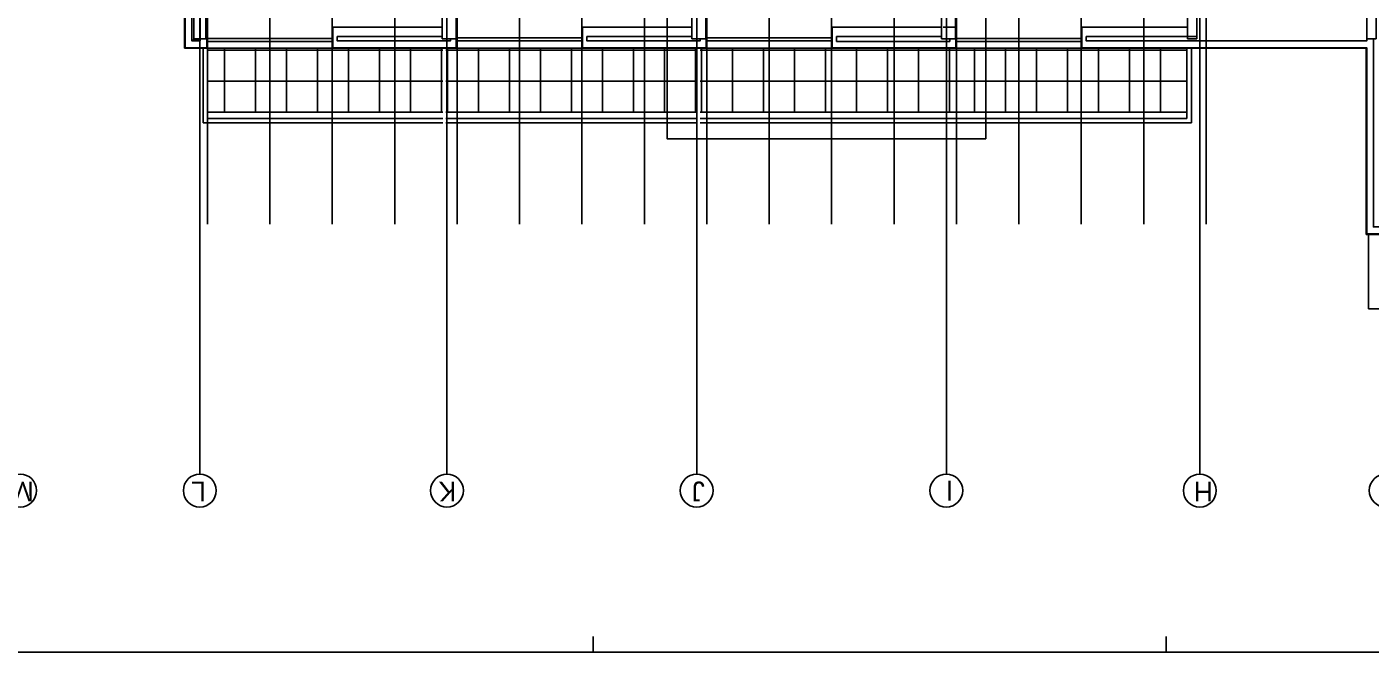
# Model space of a CAD drawing. Extents: x 1248 to 1356, y -443 to -224.
# Drawn here: x 1296.63 to 1318.31, y -253.66 to -243.58 of the extents above; entities that cross this region are included whole.
import ezdxf

# ---------------------------------------------------------------- set-up
doc = ezdxf.new("R2010")
doc.units = 0
for name, color, linetype in [('corte', 7, 'Continuous'), ('estereoctomias', 7, 'Continuous'), ('estrutura-eixos', 7, 'Continuous'), ('Level 1', 7, 'Continuous'), ('Level 10', 7, 'Continuous'), ('Level 2', 7, 'Continuous'), ('Level 40', 7, 'Continuous'), ('Level 59', 7, 'Continuous'), ('Level 62', 7, 'Continuous'), ('revestimentos', 7, 'Continuous'), ('vermelhos-cont', 7, 'Continuous'), ('vermelhos-tracej', 7, 'Continuous')]:
    doc.layers.add(name, color=color, linetype=linetype)

msp = doc.modelspace()

# ---------------------------------------------------------------- linework, layer by layer
at = {"layer": 'corte'}
for p, q in [((1299.423, -238.844), (1299.423, -243.794)), ((1299.533, -243.914), (1299.533, -238.914)), ((1303.562, -243.914), (1303.562, -238.844)), ((1307.592, -243.914), (1307.592, -238.844)), ((1311.622, -243.914), (1311.622, -238.844)), ((1315.513, -238.796), (1315.513, -243.771)), ((1311.389, -240.756), (1311.389, -243.584)), ((1303.329, -243.734), (1301.637, -243.734)), ((1303.464, -243.804), (1301.637, -243.804)), ((1303.464, -243.771), (1303.464, -243.804)), ((1307.359, -243.734), (1305.667, -243.734)), ((1307.494, -243.804), (1305.667, -243.804)), ((1307.494, -243.771), (1307.494, -243.804)), ((1311.389, -243.734), (1309.697, -243.734)), ((1311.524, -243.814), (1309.697, -243.814)), ((1311.524, -243.771), (1311.524, -243.814)), ((1315.513, -243.734), (1313.727, -243.734)), ((1318.254, -243.804), (1318.254, -243.771)), ((1319.284, -246.914), (1318.254, -246.914))]:
    msp.add_line(p, q, dxfattribs=at)
msp.add_lwpolyline([(1299.519, -238.726), (1299.519, -243.774), (1299.321, -243.774), (1299.321, -238.726)], dxfattribs=at)
for points in [[(1315.513, -243.771), (1315.363, -243.771), (1315.363, -241.471), (1315.513, -241.471)], [(1318.404, -243.771), (1318.254, -243.771), (1318.254, -242.171), (1318.404, -242.171)], [(1303.329, -243.771), (1303.559, -243.771), (1303.559, -242.771), (1303.329, -242.771)], [(1307.359, -243.771), (1307.589, -243.771), (1307.589, -242.771), (1307.359, -242.771)], [(1311.389, -243.771), (1311.619, -243.771), (1311.619, -242.771), (1311.389, -242.771)]]:
    msp.add_lwpolyline(points, close=True, dxfattribs=at)
at = {"layer": 'estereoctomias'}
for points in [[(1299.533, -238.914), (1299.983, -238.914), (1299.983, -238.726), (1299.519, -238.726), (1299.519, -238.796), (1299.913, -238.796), (1299.913, -238.844), (1299.519, -238.844), (1299.519, -243.774), (1299.423, -243.774), (1299.423, -243.804), (1299.291, -243.804), (1299.291, -238.796), (1299.321, -238.796), (1299.321, -238.726), (1299.181, -238.726), (1299.181, -243.914), (1299.519, -243.914), (1299.533, -243.914), (1299.53, -240.996), (1299.94, -240.996), (1299.94, -240.926), (1299.533, -240.926)], [(1303.559, -243.771), (1303.559, -243.914), (1301.567, -243.914), (1301.567, -243.584), (1303.329, -243.584), (1303.329, -243.734), (1301.637, -243.734), (1301.637, -243.804), (1303.464, -243.804), (1303.464, -243.771)], [(1307.592, -243.914), (1307.592, -243.771), (1307.494, -243.771), (1307.494, -243.804), (1305.667, -243.804), (1305.667, -243.734), (1307.359, -243.734), (1307.359, -243.584), (1305.597, -243.584), (1305.597, -243.914)], [(1311.524, -243.771), (1311.524, -243.814), (1309.697, -243.814), (1309.697, -243.734), (1311.389, -243.734), (1311.389, -243.584), (1309.627, -243.584), (1309.627, -243.914), (1311.622, -243.914), (1311.622, -243.771)], [(1315.363, -243.584), (1315.363, -243.734), (1313.727, -243.734), (1313.727, -243.804), (1318.254, -243.804), (1318.254, -243.771), (1318.364, -243.771), (1318.363, -246.804), (1319.214, -246.804), (1319.214, -246.734), (1318.63, -246.734), (1318.631, -246.584), (1319.284, -246.584), (1319.284, -246.914), (1318.254, -246.914), (1318.254, -243.914), (1313.657, -243.914), (1313.657, -243.584)]]:
    msp.add_lwpolyline(points, close=True, dxfattribs=at)
at = {"layer": 'estrutura-eixos'}
msp.add_line((1318.283, -246.924), (1318.283, -248.124), dxfattribs=at)
at = {"layer": 'Level 1'}
for p, q in [((1299.181, -243.914), (1299.181, -238.726)), ((1299.291, -243.794), (1299.291, -238.796)), ((1303.329, -243.584), (1301.567, -243.584)), ((1301.567, -243.584), (1301.567, -243.914)), ((1307.359, -243.584), (1305.597, -243.584)), ((1305.597, -243.584), (1305.597, -243.914)), ((1311.389, -243.584), (1309.627, -243.584)), ((1309.627, -243.584), (1309.627, -243.914)), ((1311.418, -243.584), (1311.558, -243.584)), ((1311.483, -243.584), (1311.623, -243.584)), ((1315.363, -243.584), (1313.657, -243.584)), ((1313.657, -243.584), (1313.657, -243.914)), ((1299.291, -243.794), (1299.423, -243.794)), ((1301.637, -243.734), (1301.637, -243.804)), ((1305.667, -243.734), (1305.667, -243.804)), ((1309.697, -243.734), (1309.697, -243.814)), ((1313.727, -243.734), (1313.727, -243.804)), ((1313.727, -243.804), (1318.254, -243.804)), ((1299.181, -243.914), (1299.533, -243.914)), ((1301.567, -243.914), (1303.562, -243.914)), ((1303.224, -243.914), (1303.424, -243.914)), ((1305.597, -243.914), (1307.592, -243.914)), ((1309.627, -243.914), (1311.622, -243.914)), ((1313.657, -243.914), (1318.254, -243.914)), ((1318.254, -243.914), (1318.254, -246.914))]:
    msp.add_line(p, q, dxfattribs=at)
at = {"layer": 'Level 10'}
for p, q in [((1299.542, -243.954), (1303.343, -243.954)), ((1299.818, -244.954), (1299.818, -243.924)), ((1300.318, -244.954), (1300.318, -243.924)), ((1300.818, -244.954), (1300.818, -243.924)), ((1301.318, -244.954), (1301.318, -243.924)), ((1301.818, -244.954), (1301.818, -243.924)), ((1302.318, -244.954), (1302.318, -243.924)), ((1302.818, -244.954), (1302.818, -243.924)), ((1303.318, -244.954), (1303.318, -243.924)), ((1303.393, -243.954), (1307.443, -243.954)), ((1303.418, -244.954), (1303.418, -243.924)), ((1303.918, -244.954), (1303.918, -243.924)), ((1304.418, -244.954), (1304.418, -243.924)), ((1304.918, -244.954), (1304.918, -243.924)), ((1305.418, -244.954), (1305.418, -243.924)), ((1305.918, -244.954), (1305.918, -243.924)), ((1306.418, -244.954), (1306.418, -243.924)), ((1306.918, -244.954), (1306.918, -243.924)), ((1307.418, -244.954), (1307.418, -243.924)), ((1307.493, -243.954), (1311.543, -243.954)), ((1307.518, -244.954), (1307.518, -243.924)), ((1308.018, -244.954), (1308.018, -243.924)), ((1308.518, -244.954), (1308.518, -243.924)), ((1309.018, -244.954), (1309.018, -243.924)), ((1309.518, -244.954), (1309.518, -243.924)), ((1310.018, -244.954), (1310.018, -243.924)), ((1310.518, -244.954), (1310.518, -243.924)), ((1311.018, -244.954), (1311.018, -243.924)), ((1311.518, -244.954), (1311.518, -243.924)), ((1315.353, -243.954), (1311.543, -243.954)), ((1311.923, -244.954), (1311.923, -243.924)), ((1312.423, -244.954), (1312.423, -243.924)), ((1312.923, -244.954), (1312.923, -243.924)), ((1313.423, -244.954), (1313.423, -243.924)), ((1313.923, -244.954), (1313.923, -243.924)), ((1314.423, -244.954), (1314.423, -243.924)), ((1314.923, -244.954), (1314.923, -243.924)), ((1299.542, -244.454), (1303.343, -244.454)), ((1303.393, -244.454), (1307.443, -244.454)), ((1307.493, -244.454), (1311.543, -244.454)), ((1315.353, -244.454), (1311.543, -244.454)), ((1299.542, -244.954), (1303.343, -244.954)), ((1303.393, -244.954), (1307.443, -244.954)), ((1307.493, -244.954), (1311.543, -244.954)), ((1315.353, -244.954), (1311.543, -244.954))]:
    msp.add_line(p, q, dxfattribs=at)
at = {"layer": 'Level 2'}
for p, q in [((1301.557, -243.764), (1299.543, -243.764)), ((1301.557, -243.814), (1299.543, -243.814)), ((1305.587, -243.754), (1303.572, -243.754)), ((1305.587, -243.804), (1303.572, -243.804)), ((1309.617, -243.754), (1307.602, -243.754)), ((1309.617, -243.804), (1307.602, -243.804)), ((1313.647, -243.764), (1311.632, -243.764)), ((1313.647, -243.814), (1311.632, -243.814)), ((1299.472, -245.124), (1299.472, -243.924)), ((1299.542, -245.054), (1299.542, -243.924)), ((1301.557, -243.924), (1299.543, -243.924)), ((1305.587, -243.924), (1303.572, -243.924)), ((1309.617, -243.924), (1307.602, -243.924)), ((1313.647, -243.924), (1311.632, -243.924)), ((1315.353, -245.054), (1315.353, -243.924)), ((1315.423, -245.124), (1315.423, -243.924)), ((1299.542, -245.124), (1299.472, -245.124)), ((1299.542, -245.054), (1303.343, -245.054)), ((1299.542, -245.124), (1303.343, -245.124)), ((1303.393, -245.054), (1307.443, -245.054)), ((1303.393, -245.124), (1307.443, -245.124)), ((1307.493, -245.054), (1311.543, -245.054)), ((1307.493, -245.124), (1311.543, -245.124)), ((1315.353, -245.054), (1311.543, -245.054)), ((1315.423, -245.124), (1311.543, -245.124)), ((1318.283, -248.124), (1323.893, -248.124))]:
    msp.add_line(p, q, dxfattribs=at)
at = {"layer": 'Level 40'}
for centre in [(1296.52, -251.055), (1299.419, -251.055), (1303.409, -251.055), (1307.439, -251.055), (1311.469, -251.055), (1315.559, -251.055), (1318.559, -251.055)]:
    msp.add_circle(centre, 0.265, dxfattribs=at)
at = {"layer": 'Level 59'}
msp.add_lwpolyline([(1312.108, -245.385), (1306.965, -245.385), (1306.965, -230.433), (1312.108, -230.433)], close=True, dxfattribs=at)
at = {"layer": 'Level 62'}
for p, q in [((1305.766, -253.409), (1305.766, -253.659)), ((1315.016, -253.409), (1315.016, -253.659))]:
    msp.add_line(p, q, dxfattribs=at)
msp.add_lwpolyline([(1355.966, -223.959), (1355.966, -253.659), (1278.016, -253.659), (1278.016, -223.959)], close=True, dxfattribs=at)
at = {"layer": 'revestimentos'}
for p, q in [((1299.171, -243.924), (1299.171, -238.716)), ((1299.543, -243.924), (1299.543, -241.006)), ((1303.572, -243.924), (1303.572, -241.006)), ((1307.602, -243.924), (1307.602, -241.006)), ((1311.632, -243.924), (1311.632, -241.006)), ((1301.557, -243.574), (1301.557, -243.924)), ((1305.587, -243.574), (1305.587, -243.924)), ((1309.617, -243.574), (1309.617, -243.924)), ((1313.647, -243.574), (1313.647, -243.924)), ((1299.543, -243.924), (1299.171, -243.924)), ((1303.572, -243.924), (1301.557, -243.924)), ((1307.602, -243.924), (1305.587, -243.924)), ((1311.632, -243.924), (1309.617, -243.924)), ((1313.647, -243.924), (1318.244, -243.924)), ((1318.244, -243.924), (1318.244, -246.924)), ((1319.294, -246.924), (1318.244, -246.924))]:
    msp.add_line(p, q, dxfattribs=at)
at = {"layer": 'vermelhos-cont'}
for p, q in [((1299.42, -250.792), (1299.42, -225.567)), ((1303.409, -250.792), (1303.409, -229.609)), ((1307.439, -250.792), (1307.439, -229.62)), ((1311.469, -250.792), (1311.469, -229.62)), ((1315.559, -250.792), (1315.559, -229.62))]:
    msp.add_line(p, q, dxfattribs=at)
at = {"layer": 'vermelhos-tracej'}
for p, q in [((1299.542, -246.757), (1299.542, -236.141)), ((1300.55, -246.757), (1300.55, -236.141)), ((1301.557, -246.757), (1301.557, -236.141)), ((1302.565, -246.757), (1302.565, -236.141)), ((1303.572, -246.757), (1303.572, -236.141)), ((1304.58, -246.757), (1304.58, -236.141)), ((1305.587, -246.757), (1305.587, -236.141)), ((1306.595, -246.757), (1306.595, -236.141)), ((1307.602, -246.757), (1307.602, -236.141)), ((1308.61, -246.757), (1308.61, -236.141)), ((1309.617, -246.757), (1309.617, -236.141)), ((1310.625, -246.757), (1310.625, -236.141)), ((1311.632, -246.757), (1311.632, -236.141)), ((1312.64, -246.757), (1312.64, -236.141)), ((1313.647, -246.757), (1313.647, -236.141)), ((1314.655, -246.757), (1314.655, -236.141)), ((1315.662, -246.757), (1315.662, -236.141))]:
    msp.add_line(p, q, dxfattribs=at)

# ---------------------------------------------------------------- texts
at = {"layer": 'Level 40'}
for s, p in [('M', (1296.741, -250.909)), ('L', (1299.519, -250.909)), ('K', (1303.558, -250.909)), ('J', (1307.571, -250.909)), ('I', (1311.578, -250.897)), ('H', (1315.771, -250.909))]:
    msp.add_text(s, height=0.32, rotation=180, dxfattribs=at).set_placement(p)

doc.saveas('drawing.dxf')
